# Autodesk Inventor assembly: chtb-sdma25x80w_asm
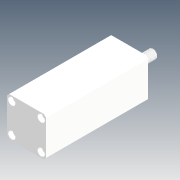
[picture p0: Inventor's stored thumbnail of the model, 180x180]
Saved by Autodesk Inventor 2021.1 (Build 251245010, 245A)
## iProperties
Company: Microsoft
Created: 2018-05
Part Number: chtb-sdma25x80w_asm
Description: STEP AP214
Document SubType Name: Assembly
Designer: user
Title: chtb-sdma25x80w_asm.STEP
Author: Windows
Revision Number: ÈÎºÎ
Sending System: SolidWorks 2015
Preprocessor: SwSTEP 2.0
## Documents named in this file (4)
- D:\Vault_2016\Projekty\Clamptek\Hydraulic\CHTB\CHTB-25\Inventor\chtb-sdma25x80w\chtb-sdma25x80w_asm.iam
- D:\Vault_2016\Projekty\Clamptek\Hydraulic\CHTB\CHTB-25\Inventor\chtb-sdma25x80w\CHTB-25QG.ipt
- D:\Vault_2016\Projekty\Clamptek\Hydraulic\CHTB\CHTB-25\Inventor\chtb-sdma25x80w\CHTB-SDMA25X80NBT.ipt
- D:\Vault_2016\Projekty\Clamptek\Hydraulic\CHTB\CHTB-25\Inventor\chtb-sdma25x80w\CHTB-SDMA25X80WHSG.ipt
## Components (3 placed, 3 different names)
1. CHTB-25QG_1
2. CHTB-SDMA25X80NBT_2
3. CHTB-SDMA25X80WHSG_3
